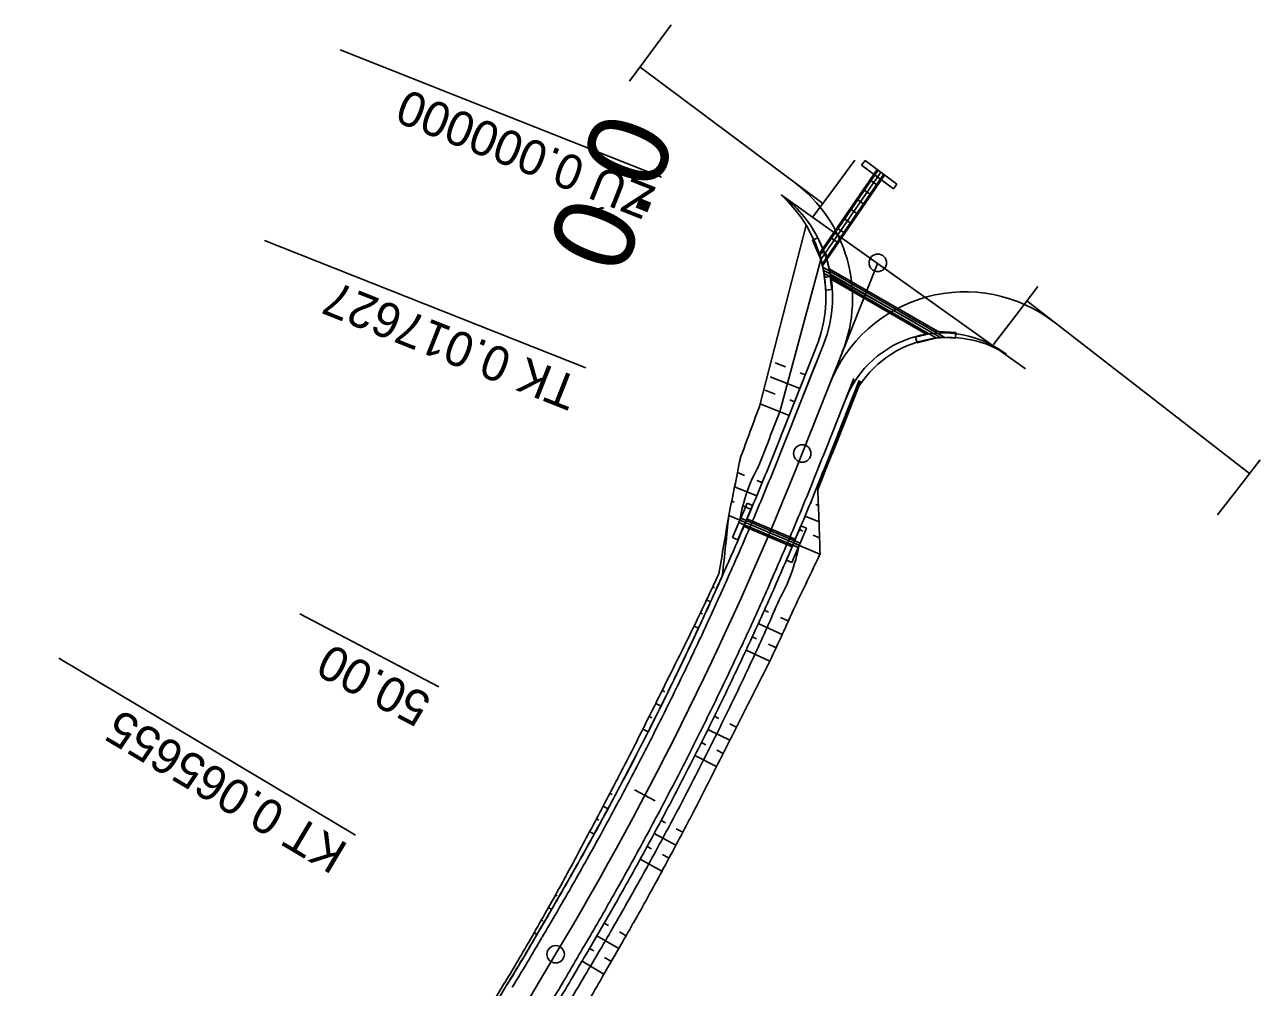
# Model space of a CAD drawing. Extents: x -481656 to -478728, y -1113199 to -1110710.
# Drawn here: x -479519.7 to -479413.6, y -1112428.2 to -1112345.5 of the extents above; entities that cross this region are included whole.
import ezdxf

# ---------------------------------------------------------------- set-up
doc = ezdxf.new("R2010")
doc.units = 0
for name, color, linetype in [('C1_HATCH_SLOPE_L', 7, 'Continuous'), ('C1_HATCH_SLOPE_R', 7, 'Continuous'), ('C1_HECTOMETRY', 7, 'Continuous'), ('C1_HLBODY', 7, 'Continuous'), ('C1_HRANA_TELESO', 7, 'Continuous'), ('C1_KORUNA', 7, 'Continuous'), ('C1_OSA', 7, 'Continuous'), ('C1_PRIKOP', 7, 'Continuous'), ('C1_STANICENI', 7, 'Continuous'), ('C1_VOZOVKA', 7, 'Continuous'), ('C1_ZPEVKRAJ', 7, 'Continuous'), ('křižovatky', 7, 'Continuous'), ('pomoc', 7, 'Continuous'), ('PROPUSTEK', 7, 'Continuous'), ('ŽLAB', 7, 'Continuous')]:
    doc.layers.add(name, color=color, linetype=linetype)

# ---------------------------------------------------------------- blocks, each defined once
blk = doc.blocks.new('A$C716')
at = {"layer": 'ŽLAB'}
for p, q in [((-5.015, 2.333), (-4.471, 3.623)), ((-4.01, 3.428), (-4.554, 2.138)), ((-4.01, 3.428), (-4.471, 3.623)), ((-5.17, 1.964), (-5.015, 2.333)), ((0, 0), (-5.093, 2.148)), ((-5.015, 2.333), (-0.383, 0.379)), ((-4.554, 2.138), (-5.015, 2.333)), ((-0.325, 0.517), (-4.496, 2.277)), ((-5.715, 0.674), (-5.17, 1.964)), ((-4.71, 1.77), (-5.254, 0.48)), ((-0.078, -0.184), (-5.171, 1.964)), ((-4.71, 1.77), (-5.17, 1.964)), ((-4.768, 1.632), (-0.597, -0.128)), ((0.161, 1.669), (-0.383, 0.379)), ((0.078, 0.184), (0.622, 1.474)), ((0.161, 1.669), (0.622, 1.474)), ((-5.254, 0.48), (-5.715, 0.674)), ((-0.538, 0.01), (-1.083, -1.28)), ((-0.078, -0.184), (-0.999, 0.204)), ((0.078, 0.184), (-0.844, 0.573)), ((-0.538, 0.01), (-0.383, 0.379)), ((-0.078, -0.184), (0.078, 0.184)), ((-0.622, -1.474), (-0.078, -0.184)), ((-1.083, -1.28), (-0.622, -1.474))]:
    blk.add_line(p, q, dxfattribs=at)

msp = doc.modelspace()

# ---------------------------------------------------------------- linework, layer by layer
at = {"layer": 'C1_HATCH_SLOPE_L'}
for p, q in [((-479448.47, -1112377.27), (-479448.47, -1112377.27)), ((-479448.4, -1112377.29), (-479448.34, -1112377.32)), ((-479448.93, -1112378.43), (-479448.8, -1112378.48)), ((-479449.39, -1112379.59), (-479449.39, -1112379.59)), ((-479449.32, -1112379.62), (-479449.26, -1112379.64)), ((-479449.85, -1112380.75), (-479449.72, -1112380.81)), ((-479452.19, -1112386.58), (-479452.08, -1112386.62)), ((-479451.75, -1112386.76), (-479451.52, -1112386.85)), ((-479452.67, -1112387.75), (-479451.47, -1112388.24)), ((-479453.15, -1112388.91), (-479452.85, -1112389.04)), ((-479451.98, -1112389.4), (-479451.43, -1112389.63)), ((-479453.64, -1112390.07), (-479451.39, -1112391.02)), ((-479456.17, -1112395.84), (-479455.8, -1112396)), ((-479454.77, -1112396.47), (-479454.11, -1112396.76)), ((-479456.69, -1112396.98), (-479454.63, -1112397.92)), ((-479457.21, -1112398.13), (-479456.83, -1112398.3)), ((-479455.81, -1112398.77), (-479455.16, -1112399.07)), ((-479457.74, -1112399.27), (-479455.7, -1112400.22)), ((-479460.45, -1112404.95), (-479460.08, -1112405.14)), ((-479461.01, -1112406.08), (-479459.13, -1112407.02)), ((-479459.13, -1112405.6), (-479458.56, -1112405.89)), ((-479461.57, -1112407.21), (-479461.2, -1112407.4)), ((-479462.14, -1112408.34), (-479460.28, -1112409.28)), ((-479460.26, -1112407.87), (-479459.7, -1112408.15)), ((-479465.04, -1112413.92), (-479464.67, -1112414.12)), ((-479463.74, -1112414.62), (-479463.17, -1112414.92)), ((-479465.63, -1112415.03), (-479463.77, -1112416.04)), ((-479466.23, -1112416.14), (-479465.86, -1112416.34)), ((-479464.93, -1112416.85), (-479464.36, -1112417.16)), ((-479466.84, -1112417.25), (-479464.97, -1112418.27)), ((-479469.92, -1112422.74), (-479469.56, -1112422.95)), ((-479470.55, -1112423.83), (-479468.67, -1112424.92)), ((-479468.62, -1112423.49), (-479468.04, -1112423.82)), ((-479471.19, -1112424.91), (-479470.83, -1112425.12)), ((-479471.83, -1112426), (-479469.95, -1112427.11)), ((-479469.89, -1112425.68), (-479469.31, -1112426.02))]:
    msp.add_line(p, q, dxfattribs=at)
at = {"layer": 'C1_HATCH_SLOPE_R'}
for p, q in [((-479454.36, -1112374.93), (-479455.23, -1112374.59)), ((-479452.66, -1112375.61), (-479453.08, -1112375.44)), ((-479453.12, -1112376.77), (-479455.66, -1112375.77)), ((-479455.24, -1112377.27), (-479456.09, -1112376.94)), ((-479453.58, -1112377.93), (-479453.99, -1112377.77)), ((-479454.04, -1112379.1), (-479456.52, -1112378.11)), ((-479457.88, -1112384.25), (-479458.48, -1112384)), ((-479456.82, -1112386.02), (-479458.72, -1112385.23)), ((-479456.35, -1112384.87), (-479456.82, -1112384.68)), ((-479458.77, -1112386.55), (-479458.97, -1112386.46)), ((-479457.3, -1112387.17), (-479457.94, -1112386.9)), ((-479457.79, -1112388.31), (-479459.23, -1112387.69)), ((-479460.44, -1112393.91), (-479460.6, -1112393.84)), ((-479460.27, -1112393.99), (-479460.28, -1112393.99)), ((-479460.78, -1112395.12), (-479461.13, -1112394.96)), ((-479461.48, -1112396.16), (-479461.66, -1112396.08)), ((-479461.3, -1112396.25), (-479461.3, -1112396.25)), ((-479461.82, -1112397.38), (-479462.2, -1112397.2)), ((-479464.72, -1112402.86), (-479464.94, -1112402.75)), ((-479464.49, -1112402.97), (-479464.5, -1112402.97)), ((-479465.04, -1112404.08), (-479465.49, -1112403.86)), ((-479465.83, -1112405.08), (-479466.05, -1112404.97)), ((-479465.59, -1112405.2), (-479465.6, -1112405.19)), ((-479466.15, -1112406.3), (-479466.61, -1112406.07)), ((-479469.23, -1112411.69), (-479469.43, -1112411.58)), ((-479469.6, -1112412.9), (-479470.01, -1112412.68)), ((-479469.01, -1112411.81), (-479469.02, -1112411.81)), ((-479470.39, -1112413.88), (-479470.59, -1112413.77)), ((-479470.78, -1112415.08), (-479471.18, -1112414.86)), ((-479470.19, -1112413.99), (-479470.19, -1112413.99)), ((-479473.97, -1112420.4), (-479474.12, -1112420.32)), ((-479473.82, -1112420.49), (-479473.83, -1112420.49)), ((-479474.44, -1112421.56), (-479474.72, -1112421.4)), ((-479475.21, -1112422.55), (-479475.33, -1112422.48)), ((-479475.07, -1112422.63), (-479475.07, -1112422.63)), ((-479475.7, -1112423.7), (-479475.95, -1112423.55))]:
    msp.add_line(p, q, dxfattribs=at)
at = {"layer": 'C1_HECTOMETRY'}
msp.add_circle((-479446.42, -1112365.98), 0.75, dxfattribs=at)
at = {"layer": 'C1_HLBODY'}
for p, q in [((-479465.01, -1112358.61), (-479492.62, -1112347.67)), ((-479471.51, -1112375), (-479499.12, -1112364.06)), ((-479491.28, -1112415.18), (-479516.79, -1112399.97))]:
    msp.add_line(p, q, dxfattribs=at)
for centre in [(-479446.42, -1112365.98), (-479452.91, -1112382.37), (-479474.1, -1112425.41)]:
    msp.add_circle(centre, 0.75, dxfattribs=at)
at = {"layer": 'C1_HRANA_TELESO'}
for p, q in [((-479452.57, -1112362.76), (-479456.52, -1112378.11)), ((-479447.88, -1112376.16), (-479449.72, -1112380.81)), ((-479478.48, -1112427.86), (-479481.04, -1112432.16))]:
    msp.add_line(p, q, dxfattribs=at)
for centre, radius, start, end in [((-480288.38, -1112074.21), 885.64, 339.60985, 339.93096), ((-480293.42, -1112047.43), 907.18, 338.12203, 338.43901), ((-479748.53, -1112326.52), 295.7, 348.0615, 349.0346), ((-479754.84, -1112398.59), 303.55, 1.4283, 2.4777), ((-479752.3, -1112340.85), 296.79, 349.9355, 350.9194), ((-479727.22, -1112261.78), 304.61, 333.9376, 334.8932), ((-479729.9, -1112267.71), 297.37, 334.187, 335.142), ((-479731.4, -1112270.94), 304.51, 334.878, 335.8329), ((-479729.78, -1112267.64), 297.29, 333.21, 334.1651), ((-479728.52, -1112265.13), 304.43, 332.7023, 333.6575), ((-479731.36, -1112270.93), 297.24, 332.9573, 333.9123), ((-479730.73, -1112269.68), 304.35, 332.698, 333.6529), ((-479732.66, -1112273.5), 297.25, 332.5591, 333.514), ((-479732.53, -1112273.24), 304.35, 332.495, 333.4499), ((-479732.63, -1112273.38), 297.28, 331.5798, 332.5348), ((-479732.53, -1112273.18), 304.37, 331.5291, 332.484), ((-479734.58, -1112276.91), 297.34, 331.4025, 332.3576), ((-479732.62, -1112273.3), 304.4, 330.6036, 331.5586), ((-479733.87, -1112275.44), 297.43, 330.1327, 331.0878), ((-479732.62, -1112273.24), 304.42, 329.6373, 330.5923), ((-479605.41, -1112350.35), 148.73, 328.5897, 330.5138), ((-479602.42, -1112352.13), 152.22, 328.6037, 330.4895)]:
    msp.add_arc(centre, radius, start, end, dxfattribs=at)
at = {"layer": 'C1_KORUNA'}
for p, q in [((-479451.54, -1112372.81), (-479454.04, -1112379.1)), ((-479448.01, -1112376.11), (-479449.85, -1112380.75)), ((-479478.26, -1112427.99), (-479480.82, -1112432.29))]:
    msp.add_line(p, q, dxfattribs=at)
for centre, radius, start, end in [((-480284.76, -1112050.78), 893.25, 338.11542, 338.43499), ((-480293.12, -1112047.44), 906.75, 338.11583, 338.43289), ((-479731.81, -1112271.84), 297.75, 336.9742, 337.9291), ((-479731.81, -1112271.84), 302.25, 336.9742, 337.9291), ((-479731.81, -1112271.84), 297.75, 336.0193, 336.9742), ((-479731.81, -1112271.84), 302.25, 336.0193, 336.9742), ((-479731.81, -1112271.84), 297.75, 335.0643, 336.0193), ((-479731.81, -1112271.84), 302.25, 335.0643, 336.0193), ((-479731.81, -1112271.84), 297.75, 334.1094, 335.0643), ((-479731.81, -1112271.84), 302.25, 334.1094, 335.0643), ((-479731.81, -1112271.84), 297.75, 333.1545, 334.1094), ((-479731.81, -1112271.84), 302.25, 333.1545, 334.1094), ((-479731.81, -1112271.84), 297.75, 332.1995, 333.1545), ((-479731.81, -1112271.84), 302.25, 332.1995, 333.1545), ((-479731.81, -1112271.84), 297.75, 331.2446, 332.1995), ((-479731.81, -1112271.84), 302.25, 331.2446, 332.1995), ((-479731.81, -1112271.84), 297.75, 330.2897, 331.2446), ((-479731.81, -1112271.84), 302.25, 330.2897, 331.2446), ((-479731.81, -1112271.84), 297.75, 329.3347, 330.2897), ((-479731.81, -1112271.84), 302.25, 329.3347, 330.2897), ((-479604.86, -1112349.67), 148.88, 328.2565, 330.179), ((-479602.93, -1112350.82), 151.12, 328.2691, 330.1666)]:
    msp.add_arc(centre, radius, start, end, dxfattribs=at)
at = {"layer": 'C1_OSA'}
for p, q in [((-479446.42, -1112365.98), (-479452.91, -1112382.37)), ((-479474.1, -1112425.41), (-479519.71, -1112501.96))]:
    msp.add_line(p, q, dxfattribs=at)
msp.add_arc((-479731.81, -1112271.84), 300, 329.2096, 338.3823, dxfattribs=at)
at = {"layer": 'C1_PRIKOP'}
for p, q in [((-479451.3, -1112365.7), (-479454.85, -1112378.78)), ((-479448, -1112376.11), (-479449.85, -1112380.76)), ((-479478.27, -1112427.99), (-479480.82, -1112432.28))]:
    msp.add_line(p, q, dxfattribs=at)
for centre, radius, start, end in [((-480286.21, -1112058.91), 890.78, 338.63608, 338.95613), ((-480293.14, -1112047.43), 906.78, 338.11583, 338.43288), ((-479444.56, -1112390.23), 13.87, 150.585, 171.1801), ((-479754.79, -1112358.91), 296.96, 353.4357, 354.4366), ((-479468.8, -1112387.22), 15.91, 330.6869, 348.9826), ((-479731.81, -1112271.84), 297.74, 335.0643, 336.0193), ((-479732.87, -1112274.2), 303.07, 335.5529, 336.5079), ((-479731.81, -1112271.84), 297.74, 334.1094, 335.0643), ((-479731.81, -1112271.84), 303.09, 334.1094, 335.0643), ((-479731.81, -1112271.84), 297.74, 333.1545, 334.1094), ((-479731.81, -1112271.84), 303.09, 333.1545, 334.1094), ((-479731.81, -1112271.84), 297.74, 332.1995, 333.1545), ((-479731.81, -1112271.84), 303.09, 332.1995, 333.1545), ((-479731.81, -1112271.84), 297.74, 331.2446, 332.1995), ((-479731.81, -1112271.84), 303.09, 331.2446, 332.1995), ((-479731.81, -1112271.84), 297.74, 330.2897, 331.2446), ((-479731.81, -1112271.84), 303.09, 330.2897, 331.2446), ((-479731.81, -1112271.84), 297.74, 329.3347, 330.2897), ((-479731.81, -1112271.84), 303.09, 329.3347, 330.2897), ((-479604.87, -1112349.67), 148.87, 328.2565, 330.179), ((-479602.57, -1112351.03), 151.54, 328.2714, 330.1644)]:
    msp.add_arc(centre, radius, start, end, dxfattribs=at)
at = {"layer": 'C1_STANICENI'}
for p, q in [((-479484.13, -1112402.43), (-479496.07, -1112396.14)), ((-479467.32, -1112411.29), (-479465.55, -1112412.23))]:
    msp.add_line(p, q, dxfattribs=at)
at = {"layer": 'C1_VOZOVKA'}
for p, q in [((-479451.73, -1112374.63), (-479453.57, -1112379.28)), ((-479448.48, -1112375.92), (-479450.32, -1112380.57))]:
    msp.add_line(p, q, dxfattribs=at)
for centre, radius, start, end in [((-480285.69, -1112050.41), 894.75, 338.11546, 338.43476), ((-480292.19, -1112047.81), 905.25, 338.11578, 338.43312), ((-479731.81, -1112271.84), 298.25, 336.9742, 337.9291), ((-479731.81, -1112271.84), 301.75, 336.9742, 337.9291), ((-479731.81, -1112271.84), 298.25, 336.0193, 336.9742), ((-479731.81, -1112271.84), 301.75, 336.0193, 336.9742), ((-479731.81, -1112271.84), 298.25, 335.0643, 336.0193), ((-479731.81, -1112271.84), 301.75, 335.0643, 336.0193), ((-479731.81, -1112271.84), 298.25, 334.1094, 335.0643), ((-479731.81, -1112271.84), 301.75, 334.1094, 335.0643), ((-479731.81, -1112271.84), 298.25, 333.1545, 334.1094), ((-479731.81, -1112271.84), 301.75, 333.1545, 334.1094), ((-479731.81, -1112271.84), 298.25, 332.1995, 333.1545), ((-479731.81, -1112271.84), 301.75, 332.1995, 333.1545), ((-479731.81, -1112271.84), 298.25, 331.2446, 332.1995), ((-479731.81, -1112271.84), 301.75, 331.2446, 332.1995), ((-479731.81, -1112271.84), 298.25, 330.2897, 331.2446), ((-479731.81, -1112271.84), 301.75, 330.2897, 331.2446), ((-479731.81, -1112271.84), 298.25, 329.3347, 330.2897), ((-479731.81, -1112271.84), 301.75, 329.3347, 330.2897), ((-479604.65, -1112349.8), 149.12, 328.2579, 330.1776), ((-479603.14, -1112350.69), 150.88, 328.2677, 330.168)]:
    msp.add_arc(centre, radius, start, end, dxfattribs=at)
at = {"layer": 'C1_ZPEVKRAJ'}
for p, q in [((-479451.08, -1112372.99), (-479453.57, -1112379.28)), ((-479448.48, -1112375.92), (-479450.32, -1112380.57))]:
    msp.add_line(p, q, dxfattribs=at)
for centre, radius, start, end in [((-480285.69, -1112050.41), 894.75, 338.11546, 338.43476), ((-480292.19, -1112047.81), 905.25, 338.11578, 338.43312), ((-479731.81, -1112271.84), 298.25, 336.9742, 337.9291), ((-479731.81, -1112271.84), 301.75, 336.9742, 337.9291), ((-479731.81, -1112271.84), 298.25, 336.0193, 336.9742), ((-479731.81, -1112271.84), 301.75, 336.0193, 336.9742), ((-479731.81, -1112271.84), 298.25, 335.0643, 336.0193), ((-479731.81, -1112271.84), 301.75, 335.0643, 336.0193), ((-479731.81, -1112271.84), 298.25, 334.1094, 335.0643), ((-479731.81, -1112271.84), 301.75, 334.1094, 335.0643), ((-479731.81, -1112271.84), 298.25, 333.1545, 334.1094), ((-479731.81, -1112271.84), 301.75, 333.1545, 334.1094), ((-479731.81, -1112271.84), 298.25, 332.1995, 333.1545), ((-479731.81, -1112271.84), 301.75, 332.1995, 333.1545), ((-479731.81, -1112271.84), 298.25, 331.2446, 332.1995), ((-479731.81, -1112271.84), 301.75, 331.2446, 332.1995), ((-479731.81, -1112271.84), 298.25, 330.2897, 331.2446), ((-479731.81, -1112271.84), 301.75, 330.2897, 331.2446), ((-479731.81, -1112271.84), 298.25, 329.3347, 330.2897), ((-479731.81, -1112271.84), 301.75, 329.3347, 330.2897), ((-479604.65, -1112349.8), 149.12, 328.2579, 330.1776), ((-479603.14, -1112350.69), 150.88, 328.2677, 330.168)]:
    msp.add_arc(centre, radius, start, end, dxfattribs=at)
at = {"layer": 'křižovatky'}
msp.add_line((-479454.71, -1112360.13), (-479433.74, -1112375.08), dxfattribs=at)
for centre, radius, start, end in [((-479461.31, -1112368.94), 11, 338.3823, 53.171), ((-479462.72, -1112368.87), 11.85, 340.5708, 47.4974), ((-479440.81, -1112381.01), 9, 52.7737, 158.3823), ((-479440.32, -1112381.56), 9.17, 57.3103, 156.3307)]:
    msp.add_arc(centre, radius, start, end, dxfattribs=at)
at = {"layer": 'pomoc'}
for p, q in [((-479465.96, -1112347.94), (-479464.16, -1112345.52)), ((-479467.75, -1112350.37), (-479465.96, -1112347.94)), ((-479466.85, -1112349.16), (-479451.15, -1112360.88)), ((-479450.23, -1112359.65), (-479448.4, -1112357.17)), ((-479452.06, -1112362.12), (-479450.23, -1112359.65)), ((-479450.48, -1112367.03), (-479443.11, -1112371.16)), ((-479432.67, -1112368.01), (-479434.57, -1112370.51)), ((-479433.62, -1112369.26), (-479414.48, -1112384.1)), ((-479434.57, -1112370.51), (-479436.47, -1112373.01)), ((-479415.39, -1112385.28), (-479413.56, -1112382.92)), ((-479417.23, -1112387.63), (-479415.39, -1112385.28))]:
    msp.add_line(p, q, dxfattribs=at)
for centre, start, end in [((-479461.09, -1112369.06), 338.3823, 53.2576), ((-479438.92, -1112380.97), 52.2213, 158.3823)]:
    msp.add_arc(centre, 12.5, start, end, dxfattribs=at)
at = {"layer": 'PROPUSTEK'}
for p, q in [((-479447.81, -1112357.6), (-479447.51, -1112357.2)), ((-479447.81, -1112357.6), (-479445.08, -1112359.63)), ((-479447.51, -1112357.2), (-479444.78, -1112359.22)), ((-479446.48, -1112357.97), (-479451.45, -1112365.21)), ((-479446.4, -1112358.02), (-479451.41, -1112365.33)), ((-479446.16, -1112358.2), (-479451.3, -1112365.7)), ((-479445.92, -1112358.38), (-479451.21, -1112366.1)), ((-479445.84, -1112358.44), (-479451.18, -1112366.24)), ((-479447.58, -1112359.74), (-479447.08, -1112360.08)), ((-479447.01, -1112358.91), (-479446.52, -1112359.25)), ((-479445.08, -1112359.63), (-479444.78, -1112359.22)), ((-479448.14, -1112360.56), (-479447.65, -1112360.9)), ((-479448.14, -1112360.56), (-479447.65, -1112360.9)), ((-479448.14, -1112360.56), (-479447.65, -1112360.9)), ((-479448.14, -1112360.56), (-479447.65, -1112360.9)), ((-479448.14, -1112360.56), (-479447.65, -1112360.9)), ((-479448.14, -1112360.56), (-479447.65, -1112360.9)), ((-479448.14, -1112360.56), (-479447.65, -1112360.9)), ((-479448.14, -1112360.56), (-479447.65, -1112360.9)), ((-479448.71, -1112361.39), (-479448.21, -1112361.73)), ((-479449.27, -1112362.21), (-479448.78, -1112362.55)), ((-479451.58, -1112363.83), (-479452.04, -1112364.03)), ((-479451.58, -1112363.83), (-479451.03, -1112365.08)), ((-479450.48, -1112363.81), (-479449.83, -1112364.26)), ((-479449.84, -1112363.04), (-479449.34, -1112363.38)), ((-479452.04, -1112364.03), (-479451.3, -1112365.7)), ((-479451.3, -1112365.7), (-479450.95, -1112367.24)), ((-479450.92, -1112365.14), (-479450.47, -1112367.13)), ((-479450.47, -1112367.13), (-479450.95, -1112367.24))]:
    msp.add_line(p, q, dxfattribs=at)
at = {"layer": 'ŽLAB'}
for p, q in [((-479450.92, -1112365.07), (-479451.41, -1112365.18)), ((-479451.41, -1112365.18), (-479451.09, -1112366.61)), ((-479450.56, -1112366.69), (-479450.92, -1112365.07)), ((-479441.4, -1112371.98), (-479451.15, -1112366.35)), ((-479451.09, -1112366.61), (-479450.87, -1112368.34)), ((-479441.1, -1112372.38), (-479451.09, -1112366.61)), ((-479451.05, -1112366.86), (-479441.38, -1112372.45)), ((-479450.6, -1112366.49), (-479441.28, -1112371.87)), ((-479450.38, -1112368.28), (-479450.51, -1112367.18)), ((-479442.21, -1112372.15), (-479450.49, -1112367.36)), ((-479450.87, -1112368.34), (-479450.38, -1112368.28)), ((-479443.18, -1112372.38), (-479442, -1112372.09)), ((-479443.05, -1112372.87), (-479443.18, -1112372.38)), ((-479441.1, -1112372.38), (-479443.05, -1112372.87)), ((-479441.62, -1112371.85), (-479439.71, -1112371.96)), ((-479440.65, -1112372.41), (-479441.4, -1112371.98)), ((-479439.74, -1112372.46), (-479441.1, -1112372.38)), ((-479439.71, -1112371.96), (-479439.74, -1112372.46))]:
    msp.add_line(p, q, dxfattribs=at)

# ---------------------------------------------------------------- block references
msp.add_blockref('A$C716', (-479453.18, -1112390.26), dxfattribs=at)

# ---------------------------------------------------------------- texts
at = {"layer": 'C1_HECTOMETRY'}
msp.add_text('0.0', height=7, rotation=68.3367, dxfattribs=at).set_placement((-479468.45, -1112367.27))
at = {"layer": 'C1_HLBODY'}
for s, rotation, p in [('ZÚ 0.000000', 158.3823, (-479465.38, -1112359.54)), ('TK 0.017627', 158.3823, (-479471.88, -1112375.93)), ('KT 0.065655', 149.2096, (-479491.79, -1112416.03))]:
    msp.add_text(s, height=3, rotation=rotation, dxfattribs=at).set_placement(p)
at = {"layer": 'C1_STANICENI'}
msp.add_text('50.00', height=3, rotation=152.1995, dxfattribs=at).set_placement((-479484.6, -1112403.32))

doc.saveas('drawing.dxf')
